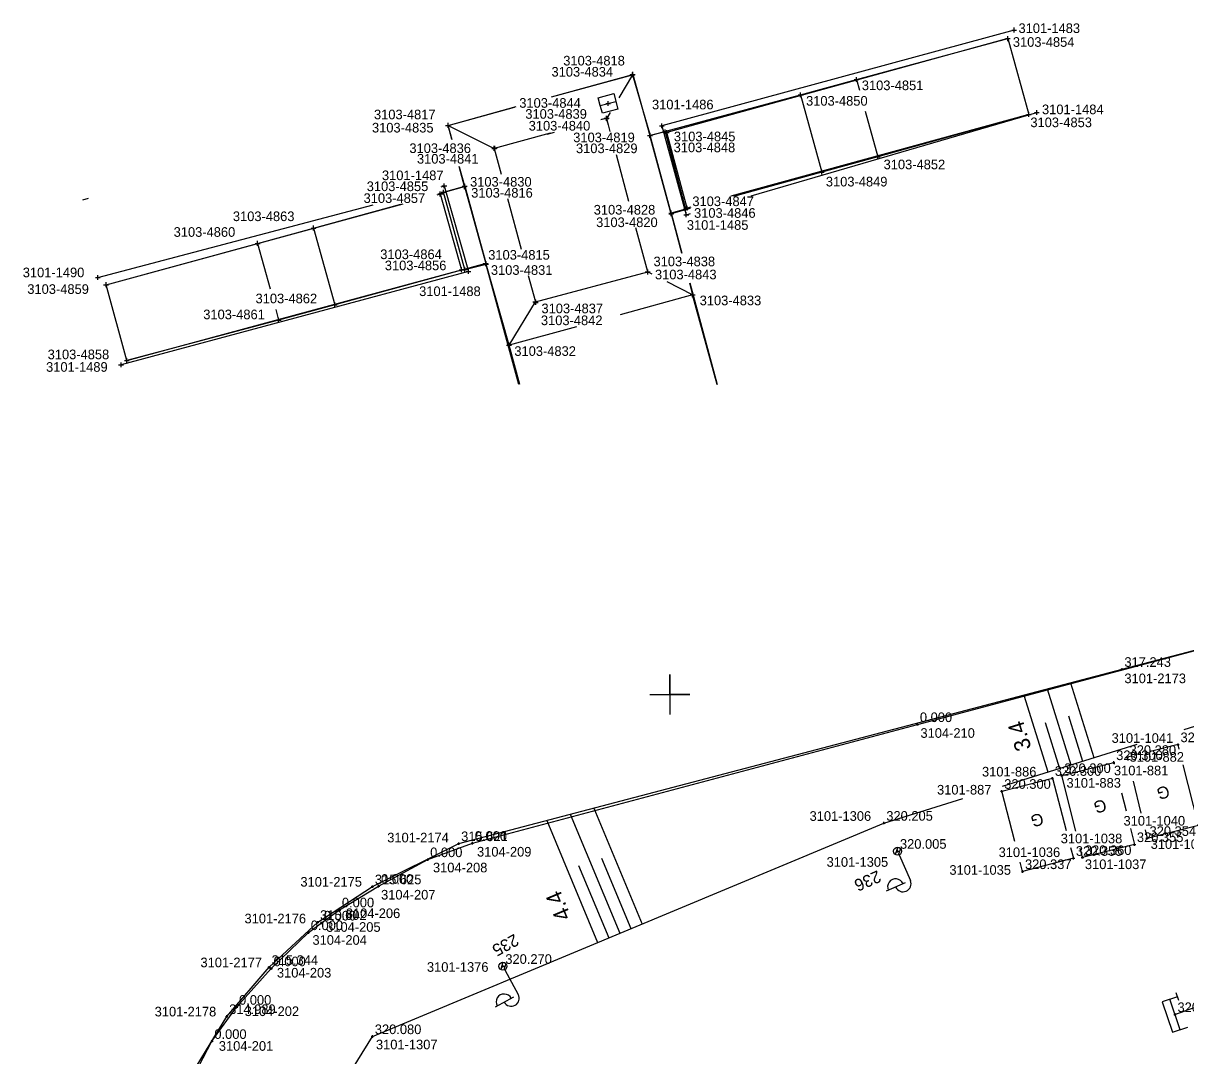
# Model space of a CAD drawing. Extents: x -821875 to -821475, y -1070280 to -1069975.
# Drawn here: x -821790.3 to -821717.8, y -1070172.5 to -1070108.2 of the extents above; entities that cross this region are included whole.
import ezdxf

# ---------------------------------------------------------------- set-up
doc = ezdxf.new("R2010")
doc.units = 0
for name, color, linetype in [('Vrstva 1', 7, 'Continuous'), ('Vrstva 14', 7, 'Continuous'), ('Vrstva 15', 7, 'Continuous'), ('Vrstva 17', 7, 'Continuous'), ('Vrstva 18', 7, 'Continuous'), ('Vrstva 23', 7, 'Continuous'), ('Vrstva 25', 7, 'Continuous'), ('Vrstva 3', 7, 'Continuous'), ('Vrstva 43', 7, 'Continuous'), ('Vrstva 48', 7, 'Continuous'), ('Vrstva 49', 7, 'Continuous'), ('Vrstva 51', 7, 'Continuous'), ('Vrstva 53', 7, 'Continuous'), ('Vrstva 60', 7, 'Continuous'), ('Vrstva 61', 7, 'Continuous')]:
    doc.layers.add(name, color=color, linetype=linetype)

# ---------------------------------------------------------------- blocks, each defined once
blk = doc.blocks.new('BOD')
at = {"layer": 'Vrstva 3'}
for p, q in [((-0.15, 0), (0.15, 0)), ((0, -0.15), (0, 0.15))]:
    blk.add_line(p, q, dxfattribs=at)

msp = doc.modelspace()

# ---------------------------------------------------------------- linework, layer by layer
at = {"layer": 'Vrstva 1'}
msp.add_lwpolyline([(-821751.25, -1070150), (-821750, -1070150), (-821750, -1070148.75), (-821750, -1070150), (-821748.75, -1070150), (-821750, -1070150), (-821750, -1070151.25)], dxfattribs=at)
for points in [[(-821515.135, -1070116.801), (-821528.933, -1070119.148), (-821545.007, -1070122.191), (-821565.452, -1070126.847), (-821593.911, -1070134.524), (-821616.729, -1070140.773), (-821646.681, -1070148.977), (-821681.98, -1070158.691), (-821694.065, -1070162.076), (-821706.535, -1070165.88), (-821718.507, -1070169.937)], [(-821679.285, -1070162.663), (-821695.528, -1070167.095), (-821716.799, -1070174.043), (-821730.799, -1070179.932), (-821744.379, -1070186.736), (-821755.356, -1070192.851), (-821764.427, -1070198.469)], [(-821677.113, -1070166.912), (-821699.427, -1070173.07), (-821715.575, -1070178.704), (-821729.749, -1070184.723), (-821746.361, -1070192.156), (-821759.601, -1070198.262)]]:
    msp.add_spline(points, degree=3, dxfattribs=at)
at = {"layer": 'Vrstva 14'}
msp.add_line((-821786.578, -1070119.16), (-821786.232, -1070119.066), dxfattribs=at)
at = {"layer": 'Vrstva 15'}
for p, q in [((-821718.186, -1070170.884), (-821718.828, -1070168.99)), ((-821718.274, -1070169.066), (-821718.435, -1070168.593))]:
    msp.add_line(p, q, dxfattribs=at)
msp.add_lwpolyline([(-821718.355, -1070168.83), (-821719.301, -1070169.151), (-821718.659, -1070171.044), (-821717.713, -1070170.723)], dxfattribs=at)
at = {"layer": 'Vrstva 17'}
for points in [[(-821728.532, -1070108.578), (-821750.494, -1070114.55), (-821748.966, -1070120.086), (-821748.696, -1070120.007)], [(-821744.927, -1070118.908), (-821727.12, -1070113.714)], [(-821764.246, -1070118.346), (-821764.05, -1070118.294), (-821762.544, -1070123.634), (-821784.194, -1070129.448)], [(-821785.642, -1070124.004), (-821768.485, -1070119.467)], [(-821785.347, -1070191.975), (-821782.414, -1070181.46), (-821781.172, -1070177.336), (-821779.748, -1070173.57), (-821777.608, -1070170.061), (-821774.963, -1070166.997), (-821771.94, -1070164.191), (-821768.526, -1070161.97), (-821763.149, -1070159.284), (-821721.814, -1070148.42), (-821694.32, -1070141.229), (-821660.419, -1070132.27), (-821642.912, -1070119.833)]]:
    msp.add_lwpolyline(points, dxfattribs=at)
at = {"layer": 'Vrstva 18'}
for points in [[(-821728.928, -1070109.116), (-821750.176, -1070114.968), (-821750.294, -1070114.926), (-821751.224, -1070115.144), (-821751.234, -1070115.15)], [(-821757.377, -1070112.741), (-821752.308, -1070111.34), (-821751.234, -1070115.15)], [(-821757.049, -1070112.668), (-821752.328, -1070111.374), (-821751.224, -1070115.144)], [(-821752.328, -1070111.374), (-821753.177, -1070112.803)], [(-821752.308, -1070111.34), (-821752.328, -1070111.374)], [(-821763.581, -1070115.374), (-821763.814, -1070114.522), (-821759.684, -1070113.39)], [(-821763.568, -1070115.423), (-821763.81, -1070114.52), (-821759.566, -1070113.347)], [(-821753.936, -1070114.082), (-821754.285, -1070114.175)], [(-821753.709, -1070114.898), (-821753.93, -1070114.07), (-821754.253, -1070114.157)], [(-821753.718, -1070113.713), (-821753.93, -1070114.07), (-821753.936, -1070114.082)], [(-821753.821, -1070114.513), (-821753.936, -1070114.082)], [(-821727.626, -1070113.842), (-821746.196, -1070118.932)], [(-821763.81, -1070114.52), (-821763.814, -1070114.522)], [(-821763.814, -1070114.522), (-821760.944, -1070115.956), (-821760.908, -1070115.95)], [(-821750.294, -1070114.926), (-821749.022, -1070119.748)], [(-821757.445, -1070115.015), (-821760.944, -1070115.956)], [(-821757.193, -1070114.955), (-821757.668, -1070115.082)], [(-821749.904, -1070119.986), (-821751.224, -1070115.144)], [(-821748.918, -1070119.678), (-821750.176, -1070114.968)], [(-821760.944, -1070115.956), (-821760.514, -1070117.557)], [(-821752.543, -1070119.268), (-821753.317, -1070116.367)], [(-821762.786, -1070118.34), (-821763.123, -1070117.084)], [(-821762.778, -1070118.31), (-821763.102, -1070117.125)], [(-821764.5, -1070118.848), (-821764.3, -1070118.794), (-821764.092, -1070118.686), (-821762.778, -1070118.31)], [(-821762.786, -1070118.34), (-821762.778, -1070118.31)], [(-821762.778, -1070118.31), (-821761.45, -1070123.162)], [(-821764.3, -1070118.794), (-821762.972, -1070123.516)], [(-821762.776, -1070123.498), (-821764.092, -1070118.686)], [(-821760.105, -1070119.078), (-821759.257, -1070122.236)], [(-821785.132, -1070124.452), (-821766.608, -1070119.421)], [(-821748.694, -1070119.616), (-821748.918, -1070119.678), (-821749.022, -1070119.748), (-821749.904, -1070119.986), (-821749.916, -1070120.036)], [(-821749.904, -1070119.986), (-821749.25, -1070122.486)], [(-821749.916, -1070120.036), (-821749.259, -1070122.464)], [(-821758.816, -1070123.876), (-821758.372, -1070125.528), (-821751.372, -1070123.656), (-821752.103, -1070120.916)], [(-821783.83, -1070129.174), (-821762.972, -1070123.516), (-821762.776, -1070123.498), (-821761.45, -1070123.162)], [(-821761.468, -1070123.134), (-821761.45, -1070123.162)], [(-821759.414, -1070130.674), (-821761.468, -1070123.134)], [(-821755.815, -1070127.073), (-821760.016, -1070128.23), (-821761.45, -1070123.162)], [(-821748.759, -1070124.363), (-821748.572, -1070125.078), (-821753.08, -1070126.32)], [(-821751.09, -1070123.799), (-821751.372, -1070123.656), (-821751.374, -1070123.672)], [(-821748.572, -1070125.078), (-821750.168, -1070124.268)], [(-821748.75, -1070124.344), (-821747.036, -1070130.674)], [(-821747.052, -1070130.674), (-821748.572, -1070125.078)], [(-821760.016, -1070128.23), (-821758.372, -1070125.528), (-821758.35, -1070125.554)], [(-821759.352, -1070130.674), (-821760.016, -1070128.23)]]:
    msp.add_lwpolyline(points, dxfattribs=at)
at = {"layer": 'Vrstva 23'}
for points in [[(-821718.246, -1070153.4), (-821718.318, -1070153.115), (-821719.956, -1070153.524)], [(-821721.204, -1070153.836), (-821721.493, -1070153.908)], [(-821721.493, -1070153.908), (-821721.444, -1070154.105)], [(-821725.563, -1070155.036), (-821722.326, -1070154.233), (-821722.3, -1070154.336)], [(-821720.377, -1070158.431), (-821720.247, -1070158.958), (-821717.052, -1070158.132), (-821717.998, -1070154.384)], [(-821729.303, -1070156.022), (-821726.152, -1070155.212), (-821725.295, -1070158.464)], [(-821724.69, -1070158.505), (-821725.563, -1070155.036)], [(-821721.127, -1070155.392), (-821720.635, -1070157.387)], [(-821728.49, -1070159.165), (-821729.303, -1070156.022)], [(-821721.849, -1070156.122), (-821721.564, -1070157.254)], [(-821721.289, -1070158.343), (-821721.037, -1070159.341), (-821724.276, -1070160.147), (-821724.419, -1070159.578)], [(-821725.016, -1070159.524), (-821724.838, -1070160.198), (-821728.009, -1070161.024), (-821728.16, -1070160.441)]]:
    msp.add_lwpolyline(points, dxfattribs=at)
at = {"layer": 'Vrstva 25'}
for p, q in [((-821735.779, -1070159.511), (-821735.954, -1070159.956)), ((-821735.611, -1070159.597), (-821735.772, -1070160.006)), ((-821735.702, -1070159.988), (-821735.003, -1070161.593)), ((-821735.324, -1070161.732), (-821736.516, -1070162.251)), ((-821760.396, -1070166.683), (-821760.531, -1070167.143)), ((-821760.221, -1070166.753), (-821760.345, -1070167.176)), ((-821760.276, -1070167.152), (-821759.437, -1070168.688)), ((-821759.744, -1070168.855), (-821760.886, -1070169.478))]:
    msp.add_line(p, q, dxfattribs=at)
for centre in [(-821735.801, -1070159.759), (-821735.801, -1070159.759), (-821760.396, -1070166.932), (-821760.396, -1070166.932)]:
    msp.add_circle(centre, 0.25, dxfattribs=at)
for centre, start, end in [((-821735.923, -1070161.986), 22.80722, 204.21236), ((-821735.462, -1070161.792), 203.50979, 23.50979), ((-821760.318, -1070169.161), 27.93945, 209.34459), ((-821759.876, -1070168.927), 208.64202, 28.64202)]:
    msp.add_arc(centre, 0.5, start, end, dxfattribs=at)
at = {"layer": 'Vrstva 43'}
msp.add_lwpolyline([(-821754.325, -1070113.28), (-821754.454, -1070112.797), (-821753.487, -1070112.54), (-821753.23, -1070113.507), (-821754.197, -1070113.764), (-821754.325, -1070113.28), (-821753.359, -1070113.024)], dxfattribs=at)
at = {"layer": 'Vrstva 48'}
for p, q in [((-821726.47, -1070149.644), (-821724.995, -1070154.376)), ((-821725.018, -1070149.262), (-821723.563, -1070153.93)), ((-821727.922, -1070150.025), (-821726.427, -1070154.823)), ((-821726.602, -1070151.741), (-821725.711, -1070154.6)), ((-821725.158, -1070151.333), (-821724.279, -1070154.153)), ((-821756.204, -1070157.459), (-821753.108, -1070164.876)), ((-821754.739, -1070157.074), (-821751.724, -1070164.299)), ((-821757.669, -1070157.844), (-821754.493, -1070165.454)), ((-821754.249, -1070160.195), (-821752.416, -1070164.588)), ((-821755.682, -1070160.657), (-821753.801, -1070165.165))]:
    msp.add_line(p, q, dxfattribs=at)
at = {"layer": 'Vrstva 49'}
for p, q in [((-821717.932, -1070152.175), (-821686.846, -1070142.486)), ((-821729.271, -1070155.709), (-821720.87, -1070153.09)), ((-821736.653, -1070158.01), (-821731.734, -1070156.477))]:
    msp.add_line(p, q, dxfattribs=at)
msp.add_lwpolyline([(-821777.907, -1070191.463), (-821775.399, -1070182.41), (-821768.529, -1070171.311), (-821736.653, -1070158.01)], dxfattribs=at)
at = {"layer": 'Vrstva 51'}
for points in [[(-821738.358, -1070111.662), (-821728.928, -1070109.116), (-821727.626, -1070113.842), (-821737.04, -1070116.476)], [(-821741.84, -1070112.622), (-821738.358, -1070111.662), (-821738.175, -1070112.332)], [(-821751.234, -1070115.15), (-821741.84, -1070112.622), (-821740.528, -1070117.432), (-821746.034, -1070118.959)], [(-821737.818, -1070113.636), (-821737.04, -1070116.476), (-821740.528, -1070117.432)], [(-821748.725, -1070119.706), (-821749.916, -1070120.036), (-821751.234, -1070115.15)], [(-821764.339, -1070118.766), (-821762.786, -1070118.34), (-821761.468, -1070123.134), (-821770.876, -1070125.698)], [(-821772.204, -1070120.92), (-821766.75, -1070119.426)], [(-821775.684, -1070121.874), (-821772.204, -1070120.92), (-821770.876, -1070125.698), (-821774.372, -1070126.658)], [(-821783.83, -1070129.174), (-821785.132, -1070124.452), (-821775.684, -1070121.874), (-821774.906, -1070124.709)], [(-821774.553, -1070125.997), (-821774.372, -1070126.658), (-821783.83, -1070129.174)]]:
    msp.add_lwpolyline(points, dxfattribs=at)
at = {"layer": 'Vrstva 53'}
msp.add_lwpolyline([(-821780.16, -1070174.72), (-821778.53, -1070171.61), (-821776.99, -1070169.48), (-821774.84, -1070167.08), (-821772.52, -1070164.83), (-821771.7, -1070164.23), (-821770.58, -1070163.41), (-821768.14, -1070161.94), (-821765.08, -1070160.28), (-821762.3, -1070159.26), (-821734.56, -1070151.86), (-821659.89, -1070131.96)], dxfattribs=at)

# ---------------------------------------------------------------- block references
at = {"layer": 'Vrstva 60'}
for p in [(-821728.532, -1070108.578), (-821728.928, -1070109.116), (-821752.328, -1070111.374), (-821752.308, -1070111.34), (-821738.358, -1070111.662), (-821741.84, -1070112.622), (-821753.842, -1070113.152), (-821753.936, -1070114.082), (-821753.93, -1070114.07), (-821727.626, -1070113.842), (-821727.12, -1070113.714), (-821763.814, -1070114.522), (-821763.81, -1070114.52), (-821750.494, -1070114.55), (-821750.294, -1070114.926), (-821750.176, -1070114.968), (-821751.234, -1070115.15), (-821751.224, -1070115.144), (-821760.944, -1070115.956), (-821760.908, -1070115.95), (-821737.04, -1070116.476), (-821740.528, -1070117.432), (-821764.092, -1070118.686), (-821764.05, -1070118.294), (-821762.786, -1070118.34), (-821762.778, -1070118.31), (-821764.3, -1070118.794), (-821749.916, -1070120.036), (-821749.904, -1070119.986), (-821749.022, -1070119.748), (-821748.966, -1070120.086), (-821748.918, -1070119.678), (-821772.204, -1070120.92), (-821775.684, -1070121.874), (-821762.972, -1070123.516), (-821762.776, -1070123.498), (-821762.544, -1070123.634), (-821761.468, -1070123.134), (-821761.45, -1070123.162), (-821751.374, -1070123.672), (-821751.372, -1070123.656), (-821785.642, -1070124.004), (-821785.132, -1070124.452), (-821748.572, -1070125.078), (-821770.876, -1070125.698), (-821758.372, -1070125.528), (-821758.35, -1070125.554), (-821774.372, -1070126.658), (-821760.016, -1070128.23), (-821784.194, -1070129.448), (-821783.83, -1070129.174)]:
    msp.add_blockref('BOD', p, dxfattribs=at)
at = {"layer": 'Vrstva 60', "xscale": 0.5, "yscale": 0.5}
for p in [(-821721.814, -1070148.42), (-821734.56, -1070151.86), (-821718.318, -1070153.115), (-821721.493, -1070153.908), (-821722.326, -1070154.233), (-821726.152, -1070155.212), (-821725.563, -1070155.036), (-821729.303, -1070156.022), (-821736.653, -1070158.01), (-821720.247, -1070158.958), (-821763.149, -1070159.284), (-821762.3, -1070159.26), (-821735.801, -1070159.759), (-821721.037, -1070159.341), (-821765.08, -1070160.28), (-821724.838, -1070160.198), (-821724.276, -1070160.147), (-821728.009, -1070161.024), (-821768.526, -1070161.97), (-821768.14, -1070161.94), (-821770.58, -1070163.41), (-821771.94, -1070164.191), (-821771.7, -1070164.23), (-821772.52, -1070164.83), (-821774.963, -1070166.997), (-821774.84, -1070167.08), (-821760.396, -1070166.932), (-821777.608, -1070170.061), (-821776.99, -1070169.48), (-821718.507, -1070169.937), (-821768.529, -1070171.311), (-821778.53, -1070171.61)]:
    msp.add_blockref('BOD', p, dxfattribs=at)

# ---------------------------------------------------------------- texts
at = {"layer": 'Vrstva 23'}
for rotation, p in [(194.0235, (-821718.959, -1070155.65)), (193.97379, (-821722.892, -1070156.506)), (194.60028, (-821726.821, -1070157.356))]:
    msp.add_text('G', height=0.75, rotation=rotation, dxfattribs=at).set_placement(p)
at = {"layer": 'Vrstva 25'}
for s, rotation, p in [('236', 203.50976, (-821737.041, -1070160.934)), ('235', 208.64189, (-821759.674, -1070164.889))]:
    msp.add_text(s, height=0.75, rotation=rotation, dxfattribs=at).set_placement(p)
at = {"layer": 'Vrstva 48'}
for s, rotation, p in [('3.4', 107.30642, (-821727.447, -1070153.334)), ('4.4', 112.653, (-821756.129, -1070163.851))]:
    msp.add_text(s, height=1, rotation=rotation, dxfattribs=at).set_placement(p)
at = {"layer": 'Vrstva 60'}
for s, p in [('3101-1483', (-821728.265, -1070108.764)), ('3103-4854', (-821728.616, -1070109.624)), ('3103-4818', (-821756.634, -1070110.788)), ('3103-4834', (-821757.368, -1070111.48)), ('3103-4851', (-821738.029, -1070112.326)), ('3103-4850', (-821741.504, -1070113.293)), ('3103-4844', (-821759.376, -1070113.422)), ('3103-4839', (-821759, -1070114.108)), ('3101-1486', (-821751.106, -1070113.522)), ('3101-1484', (-821726.799, -1070113.824)), ('3103-4817', (-821768.431, -1070114.142)), ('3103-4853', (-821727.524, -1070114.632)), ('3103-4835', (-821768.556, -1070114.964)), ('3103-4840', (-821758.79, -1070114.843)), ('3103-4845', (-821749.742, -1070115.511)), ('3103-4836', (-821766.225, -1070116.244)), ('3103-4819', (-821756.014, -1070115.571)), ('3103-4829', (-821755.842, -1070116.251)), ('3103-4848', (-821749.756, -1070116.194)), ('3103-4841', (-821765.753, -1070116.904)), ('3103-4852', (-821736.67, -1070117.256)), ('3101-1487', (-821767.934, -1070117.935)), ('3103-4830', (-821762.444, -1070118.338)), ('3103-4849', (-821740.27, -1070118.327)), ('3103-4855', (-821768.884, -1070118.617)), ('3103-4816', (-821762.372, -1070119.022)), ('3103-4857', (-821769.079, -1070119.355)), ('3103-4847', (-821748.589, -1070119.552)), ('3103-4863', (-821777.225, -1070120.487)), ('3103-4828', (-821754.737, -1070120.079)), ('3103-4846', (-821748.484, -1070120.281)), ('3103-4820', (-821754.588, -1070120.86)), ('3101-1485', (-821748.933, -1070121.03)), ('3103-4860', (-821780.916, -1070121.466)), ('3103-4864', (-821768.041, -1070122.856)), ('3103-4815', (-821761.311, -1070122.892)), ('3103-4838', (-821751.01, -1070123.302)), ('3101-1490', (-821790.32, -1070123.986)), ('3103-4856', (-821767.756, -1070123.549)), ('3103-4831', (-821761.146, -1070123.837)), ('3103-4843', (-821750.92, -1070124.116)), ('3103-4859', (-821790.036, -1070125.024)), ('3103-4862', (-821775.812, -1070125.609)), ('3101-1488', (-821765.618, -1070125.159)), ('3103-4837', (-821757.993, -1070126.23)), ('3103-4833', (-821748.134, -1070125.731)), ('3103-4861', (-821779.07, -1070126.604)), ('3103-4842', (-821758.028, -1070126.972)), ('3103-4858', (-821788.768, -1070129.096)), ('3103-4832', (-821759.684, -1070128.888)), ('3101-1489', (-821788.866, -1070129.878)), ('3101-2173', (-821721.664, -1070149.288)), ('3104-210', (-821734.375, -1070152.694)), ('3101-1041', (-821722.461, -1070153.007)), ('3101-882', (-821721.343, -1070154.184)), ('3101-886', (-821730.539, -1070155.104)), ('3101-881', (-821722.316, -1070155.032)), ('3101-883', (-821725.273, -1070155.801)), ('3101-887', (-821733.341, -1070156.229)), ('3101-1306', (-821741.284, -1070157.868)), ('3101-1040', (-821721.719, -1070158.164)), ('3101-2174', (-821767.606, -1070159.211)), ('3101-1038', (-821725.633, -1070159.268)), ('3101-1039', (-821720.028, -1070159.617)), ('3104-209', (-821762.01, -1070160.094)), ('3101-1036', (-821729.504, -1070160.125)), ('3104-208', (-821764.756, -1070161.079)), ('3101-1305', (-821740.223, -1070160.732)), ('3101-1037', (-821724.126, -1070160.876)), ('3101-1035', (-821732.571, -1070161.23)), ('3101-2175', (-821773.018, -1070161.967)), ('3104-207', (-821767.99, -1070162.773)), ('3104-206', (-821770.186, -1070163.929)), ('3101-2176', (-821776.501, -1070164.257)), ('3104-205', (-821771.411, -1070164.785)), ('3104-204', (-821772.266, -1070165.594)), ('3101-2177', (-821779.245, -1070166.993)), ('3104-203', (-821774.481, -1070167.635)), ('3101-1376', (-821765.132, -1070167.277)), ('3101-2178', (-821782.099, -1070170.058)), ('3104-202', (-821776.491, -1070170.035)), ('3104-201', (-821778.101, -1070172.2)), ('3101-1307', (-821768.309, -1070172.109))]:
    msp.add_text(s, height=0.6, dxfattribs=at).set_placement(p)
at = {"layer": 'Vrstva 61'}
for s, p in [('317.243', (-821721.664, -1070148.27)), ('0.000', (-821734.41, -1070151.71)), ('320.283', (-821718.168, -1070152.965)), ('320.280', (-821721.343, -1070153.758)), ('320.300', (-821722.176, -1070154.083)), ('320.300', (-821726.002, -1070155.062)), ('320.300', (-821725.413, -1070154.886)), ('320.300', (-821729.153, -1070155.872)), ('320.205', (-821736.503, -1070157.86)), ('320.354', (-821720.097, -1070158.808)), ('315.621', (-821762.999, -1070159.134)), ('0.000', (-821762.15, -1070159.11)), ('320.005', (-821735.651, -1070159.609)), ('320.355', (-821720.887, -1070159.191)), ('0.000', (-821764.93, -1070160.13)), ('320.355', (-821724.688, -1070160.048)), ('320.360', (-821724.126, -1070159.997)), ('320.337', (-821727.859, -1070160.874)), ('315.625', (-821768.376, -1070161.82)), ('0.000', (-821767.99, -1070161.79)), ('0.000', (-821770.43, -1070163.26)), ('315.602', (-821771.79, -1070164.041)), ('0.000', (-821771.55, -1070164.08)), ('0.000', (-821772.37, -1070164.68)), ('315.344', (-821774.813, -1070166.847)), ('0.000', (-821774.69, -1070166.93)), ('320.270', (-821760.246, -1070166.782)), ('0.000', (-821776.84, -1070169.33)), ('320.144', (-821718.357, -1070169.787)), ('314.989', (-821777.458, -1070169.911)), ('320.080', (-821768.379, -1070171.161)), ('0.000', (-821778.38, -1070171.46))]:
    msp.add_text(s, height=0.6, dxfattribs=at).set_placement(p)

doc.saveas('drawing.dxf')
